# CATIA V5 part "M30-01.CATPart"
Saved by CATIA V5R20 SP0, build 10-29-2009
Part number: M30-01
Revision: ANY
Definition: UNKNOWN
Nomenclature: M30-01
Source: Unknown
Bounding box of the stored display mesh (mm): x -15 to 15, y -15 to 15, z 0 to 290
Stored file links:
  C:\Users\Utente\Desktop\IO LAVORO\3D X SITO CF\X 3D SITO CF 27-09-2020\740T\740T-30\M30-01.CATPart
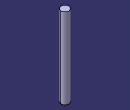
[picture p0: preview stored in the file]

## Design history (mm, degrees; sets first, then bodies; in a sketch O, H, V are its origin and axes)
Body1 "NONE" (main body)
  Solid1: solid without history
